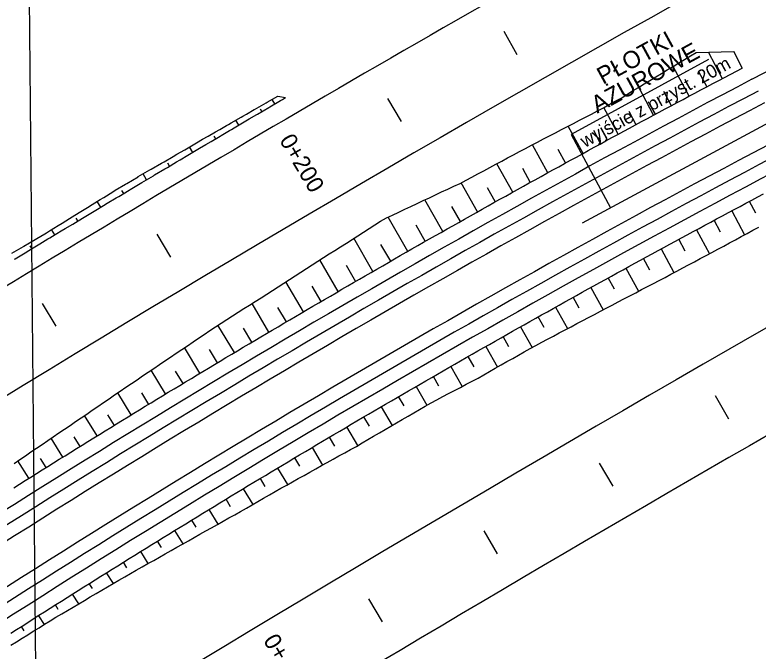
# Model space of a CAD drawing. Extents: x 6503541 to 6503743, y 5888004 to 5888145.
# Drawn here: x 6503601.663 to 6503602.995, y 5888053.81 to 5888054.951 of the extents above; entities that cross this region are included whole.
import ezdxf

# ---------------------------------------------------------------- set-up
doc = ezdxf.new("R2010")
doc.units = 0
doc.layers.add('12', color=7, linetype='Continuous')
doc.layers.add('tabela', color=7, linetype='Continuous')

msp = doc.modelspace()

# ---------------------------------------------------------------- linework, layer by layer
at = {"layer": '12'}
for p, q in [((6503602.9314, 5888054.836), (6503602.9062, 5888054.8841)), ((6503602.9669, 5888054.8556), (6503602.9514, 5888054.8851)), ((6503602.9514, 5888054.8851), (6503602.9669, 5888054.8556)), ((6503602.9065, 5888054.8707), (6503602.66, 5888054.7363)), ((6503602.9841, 5888054.8354), (6503603.0601, 5888054.8753)), ((6503602.8714, 5888054.8051), (6503602.8429, 5888054.8586)), ((6503602.8885, 5888054.8496), (6503602.9032, 5888054.822)), ((6503602.8079, 5888054.7711), (6503602.7811, 5888054.821)), ((6503602.8258, 5888054.814), (6503602.8396, 5888054.7882)), ((6503602.7446, 5888054.7369), (6503602.7187, 5888054.7847)), ((6503602.7632, 5888054.7781), (6503602.7762, 5888054.7541)), ((6503603.0226, 5888054.7621), (6503602.6797, 5888054.5776)), ((6503602.6813, 5888054.7025), (6503602.6546, 5888054.7514)), ((6503602.66, 5888054.7363), (6503602.7307, 5888054.605)), ((6503602.6998, 5888054.7439), (6503602.7129, 5888054.7197)), ((6503602.6182, 5888054.6678), (6503602.5906, 5888054.7178)), ((6503602.6362, 5888054.7099), (6503602.6498, 5888054.6852)), ((6503602.5552, 5888054.6329), (6503602.5268, 5888054.684)), ((6503602.5727, 5888054.6757), (6503602.5867, 5888054.6504)), ((6503602.4924, 5888054.5978), (6503602.4631, 5888054.6499)), ((6503602.5094, 5888054.6411), (6503602.5238, 5888054.6154)), ((6503602.4297, 5888054.5624), (6503602.3975, 5888054.6191)), ((6503602.9913, 5888054.595), (6503602.9798, 5888054.6165)), ((6503602.4457, 5888054.6073), (6503602.461, 5888054.5801)), ((6503602.3671, 5888054.5268), (6503602.332, 5888054.5882)), ((6503602.948, 5888054.5996), (6503602.971, 5888054.5565)), ((6503602.9279, 5888054.561), (6503602.9163, 5888054.5826)), ((6503602.3816, 5888054.5741), (6503602.3984, 5888054.5446)), ((6503602.8846, 5888054.5655), (6503602.9078, 5888054.5225)), ((6503602.3047, 5888054.4909), (6503602.2705, 5888054.5502)), ((6503602.8645, 5888054.527), (6503602.8529, 5888054.5484)), ((6503602.3185, 5888054.5393), (6503602.3359, 5888054.5089)), ((6503602.8213, 5888054.5312), (6503602.8444, 5888054.4887)), ((6503602.2424, 5888054.4549), (6503602.2095, 5888054.5113)), ((6503602.8012, 5888054.4929), (6503602.7897, 5888054.514)), ((6503602.2567, 5888054.5019), (6503602.2735, 5888054.4729)), ((6503602.7581, 5888054.4966), (6503602.7809, 5888054.4553)), ((6503602.1802, 5888054.4186), (6503602.1487, 5888054.4722)), ((6503602.7378, 5888054.4589), (6503602.7266, 5888054.4793)), ((6503602.1952, 5888054.4643), (6503602.2113, 5888054.4367)), ((6503602.6951, 5888054.4619), (6503602.7172, 5888054.4219)), ((6503602.6745, 5888054.4248), (6503602.6636, 5888054.4444)), ((6503602.1182, 5888054.382), (6503602.0879, 5888054.4332)), ((6503602.1338, 5888054.4264), (6503602.1492, 5888054.4003)), ((6503602.6322, 5888054.4269), (6503602.6537, 5888054.3884)), ((6503602.6114, 5888054.3904), (6503602.6008, 5888054.4093)), ((6503602.0563, 5888054.3452), (6503602.0269, 5888054.3944)), ((6503602.0722, 5888054.3888), (6503602.0872, 5888054.3637)), ((6503602.5694, 5888054.3916), (6503602.5903, 5888054.3546)), ((6503602.5485, 5888054.3555), (6503602.5381, 5888054.3739)), ((6503601.9945, 5888054.3082), (6503601.9669, 5888054.3541)), ((6503602.0111, 5888054.3505), (6503602.0254, 5888054.3268)), ((6503602.5068, 5888054.3561), (6503602.5277, 5888054.3193)), ((6503602.486, 5888054.3199), (6503602.4755, 5888054.3383)), ((6503601.9329, 5888054.271), (6503601.907, 5888054.3137)), ((6503601.9503, 5888054.3118), (6503601.9637, 5888054.2897)), ((6503602.4442, 5888054.3204), (6503602.4648, 5888054.2846)), ((6503602.423, 5888054.2851), (6503602.413, 5888054.3024)), ((6503602.3819, 5888054.2844), (6503602.4014, 5888054.2508)), ((6503601.8714, 5888054.2335), (6503601.8472, 5888054.2731)), ((6503601.8896, 5888054.2729), (6503601.9021, 5888054.2523)), ((6503602.3605, 5888054.2496), (6503602.3507, 5888054.2663)), ((6503602.3196, 5888054.2482), (6503602.3392, 5888054.2147)), ((6503601.81, 5888054.1959), (6503601.7875, 5888054.2323)), ((6503601.829, 5888054.2337), (6503601.8407, 5888054.2147)), ((6503602.2984, 5888054.2133), (6503602.2886, 5888054.23)), ((6503602.2575, 5888054.2118), (6503602.2772, 5888054.1784)), ((6503601.7488, 5888054.1579), (6503601.7278, 5888054.1917)), ((6503601.7686, 5888054.1944), (6503601.7794, 5888054.1769)), ((6503602.2362, 5888054.1772), (6503602.2265, 5888054.1935)), ((6503602.1956, 5888054.1751), (6503602.2144, 5888054.1435)), ((6503601.6878, 5888054.1198), (6503601.6682, 5888054.151)), ((6503601.7081, 5888054.1551), (6503601.7183, 5888054.1389)), ((6503602.1738, 5888054.1414), (6503602.1646, 5888054.1567)), ((6503602.1337, 5888054.1382), (6503602.1516, 5888054.1084)), ((6503602.1116, 5888054.1052), (6503602.1029, 5888054.1197)), ((6503602.072, 5888054.1011), (6503602.0892, 5888054.0728)), ((6503602.0496, 5888054.0687), (6503602.0413, 5888054.0825)), ((6503602.0105, 5888054.0637), (6503602.0265, 5888054.0374)), ((6503601.9875, 5888054.0324), (6503601.9798, 5888054.045)), ((6503601.9491, 5888054.0261), (6503601.9639, 5888054.0021)), ((6503601.9255, 5888053.9958), (6503601.9184, 5888054.0073)), ((6503601.8878, 5888053.9883), (6503601.9012, 5888053.9667)), ((6503601.8636, 5888053.9592), (6503601.8573, 5888053.9693)), ((6503601.8267, 5888053.9503), (6503601.8387, 5888053.9311)), ((6503601.802, 5888053.922), (6503601.7962, 5888053.9311)), ((6503601.7657, 5888053.912), (6503601.7768, 5888053.8945)), ((6503601.7406, 5888053.8844), (6503601.7353, 5888053.8927)), ((6503601.7049, 5888053.8734), (6503601.7151, 5888053.8574)), ((6503601.6795, 5888053.8463), (6503601.6745, 5888053.8541))]:
    msp.add_line(p, q, dxfattribs=at)
for points in [[(6503602.5635, 5888054.8792), (6503602.5397, 5888054.9209)], [(6503601.6616, 5888054.1465), (6503601.6716, 5888054.1534), (6503601.6816, 5888054.1602), (6503601.6916, 5888054.167), (6503601.7016, 5888054.1738), (6503601.7116, 5888054.1807), (6503601.7216, 5888054.1875), (6503601.7316, 5888054.1943), (6503601.7416, 5888054.2011), (6503601.7516, 5888054.2078), (6503601.7617, 5888054.2146), (6503601.7717, 5888054.2214), (6503601.7817, 5888054.2283), (6503601.7916, 5888054.2351), (6503601.8016, 5888054.242), (6503601.8116, 5888054.2488), (6503601.8216, 5888054.2557), (6503601.8316, 5888054.2625), (6503601.8416, 5888054.2693), (6503601.8516, 5888054.2762), (6503601.8616, 5888054.283), (6503601.8716, 5888054.2898), (6503601.8817, 5888054.2966), (6503601.8917, 5888054.3034), (6503601.9017, 5888054.3102), (6503601.9118, 5888054.317), (6503601.9218, 5888054.3237), (6503601.9318, 5888054.3305), (6503601.9419, 5888054.3373), (6503601.9519, 5888054.3441), (6503601.962, 5888054.3508), (6503601.972, 5888054.3576), (6503601.9821, 5888054.3644), (6503601.9921, 5888054.3711), (6503602.0022, 5888054.3779), (6503602.0123, 5888054.3846), (6503602.0223, 5888054.3914), (6503602.0324, 5888054.3981), (6503602.0426, 5888054.4047), (6503602.0528, 5888054.4111), (6503602.0631, 5888054.4176), (6503602.0733, 5888054.4241), (6503602.0836, 5888054.4305), (6503602.0938, 5888054.4369), (6503602.1041, 5888054.4434), (6503602.1143, 5888054.4499), (6503602.1245, 5888054.4565), (6503602.1346, 5888054.463), (6503602.1448, 5888054.4696), (6503602.155, 5888054.4762), (6503602.1652, 5888054.4828), (6503602.1754, 5888054.4894), (6503602.1855, 5888054.4959), (6503602.1957, 5888054.5025), (6503602.2059, 5888054.509), (6503602.2161, 5888054.5156), (6503602.2264, 5888054.5221), (6503602.2366, 5888054.5286), (6503602.2468, 5888054.5351), (6503602.257, 5888054.5417), (6503602.2672, 5888054.5482), (6503602.2775, 5888054.5547), (6503602.2877, 5888054.5612), (6503602.2979, 5888054.5677), (6503602.3082, 5888054.5742), (6503602.3184, 5888054.5807), (6503602.3289, 5888054.5867), (6503602.3399, 5888054.5919), (6503602.3509, 5888054.5971), (6503602.3618, 5888054.6023), (6503602.3728, 5888054.6075), (6503602.3838, 5888054.6127), (6503602.3948, 5888054.6178), (6503602.4058, 5888054.623), (6503602.4168, 5888054.6282), (6503602.4278, 5888054.6333), (6503602.4388, 5888054.6385), (6503602.4498, 5888054.6436), (6503602.4608, 5888054.6487), (6503602.4716, 5888054.6542), (6503602.4822, 5888054.66), (6503602.4929, 5888054.6657), (6503602.5035, 5888054.6715), (6503602.5142, 5888054.6772), (6503602.5249, 5888054.6829), (6503602.5355, 5888054.6887), (6503602.5462, 5888054.6944), (6503602.5569, 5888054.7), (6503602.5676, 5888054.7057), (6503602.5783, 5888054.7113), (6503602.589, 5888054.717), (6503602.5997, 5888054.7226), (6503602.6104, 5888054.7283), (6503602.6212, 5888054.7339), (6503602.6319, 5888054.7395), (6503602.6426, 5888054.7451), (6503602.6533, 5888054.7507), (6503602.6641, 5888054.7563), (6503602.6748, 5888054.7619), (6503602.6855, 5888054.7675), (6503602.6963, 5888054.7731), (6503602.707, 5888054.7787), (6503602.7178, 5888054.7842), (6503602.7284, 5888054.79), (6503602.739, 5888054.7959), (6503602.7495, 5888054.8018), (6503602.7599, 5888054.808), (6503602.7703, 5888054.8144), (6503602.7806, 5888054.8207), (6503602.791, 5888054.827), (6503602.8013, 5888054.8333), (6503602.8117, 5888054.8396), (6503602.822, 5888054.8459), (6503602.8324, 5888054.8522), (6503602.8428, 5888054.8585), (6503602.8531, 5888054.8648), (6503602.8635, 5888054.871), (6503602.8739, 5888054.8773), (6503602.8843, 5888054.8836), (6503602.9514, 5888054.8851)], [(6503601.6606, 5888054.1027), (6503601.6708, 5888054.1092), (6503601.681, 5888054.1156), (6503601.6913, 5888054.122), (6503601.7015, 5888054.1284), (6503601.7117, 5888054.1348), (6503601.722, 5888054.1412), (6503601.7322, 5888054.1476), (6503601.7424, 5888054.154), (6503601.7527, 5888054.1603), (6503601.7629, 5888054.1667), (6503601.7732, 5888054.1731), (6503601.7835, 5888054.1794), (6503601.7937, 5888054.1858), (6503601.804, 5888054.1921), (6503601.8142, 5888054.1985), (6503601.8245, 5888054.2048), (6503601.8348, 5888054.2111), (6503601.8451, 5888054.2174), (6503601.8554, 5888054.2238), (6503601.8657, 5888054.2301), (6503601.876, 5888054.2364), (6503601.8863, 5888054.2426), (6503601.8966, 5888054.2489), (6503601.9069, 5888054.2552), (6503601.9172, 5888054.2615), (6503601.9275, 5888054.2678), (6503601.9378, 5888054.274), (6503601.9481, 5888054.2803), (6503601.9584, 5888054.2865), (6503601.9688, 5888054.2928), (6503601.9791, 5888054.299), (6503601.9894, 5888054.3052), (6503601.9998, 5888054.3114), (6503602.0101, 5888054.3176), (6503602.0205, 5888054.3239), (6503602.0308, 5888054.3301), (6503602.0412, 5888054.3363), (6503602.0515, 5888054.3424), (6503602.0619, 5888054.3486), (6503602.0723, 5888054.3548), (6503602.0827, 5888054.361), (6503602.093, 5888054.3671), (6503602.1034, 5888054.3733), (6503602.1138, 5888054.3794), (6503602.1242, 5888054.3856), (6503602.1346, 5888054.3917), (6503602.145, 5888054.3979), (6503602.1554, 5888054.404), (6503602.1658, 5888054.4101), (6503602.1762, 5888054.4162), (6503602.1866, 5888054.4223), (6503602.197, 5888054.4284), (6503602.2074, 5888054.4345), (6503602.2178, 5888054.4406), (6503602.2283, 5888054.4467), (6503602.2387, 5888054.4527), (6503602.2491, 5888054.4588), (6503602.2596, 5888054.4649), (6503602.27, 5888054.4709), (6503602.2804, 5888054.477), (6503602.2909, 5888054.483), (6503602.3013, 5888054.489), (6503602.3118, 5888054.4951), (6503602.3223, 5888054.5011), (6503602.3327, 5888054.5071), (6503602.3432, 5888054.5131), (6503602.3537, 5888054.5191), (6503602.3641, 5888054.5251), (6503602.3746, 5888054.5311), (6503602.3851, 5888054.5371), (6503602.3956, 5888054.543), (6503602.4061, 5888054.549), (6503602.4166, 5888054.555), (6503602.4271, 5888054.5609), (6503602.4376, 5888054.5669), (6503602.4481, 5888054.5728), (6503602.4586, 5888054.5787), (6503602.4691, 5888054.5847), (6503602.4796, 5888054.5906), (6503602.4901, 5888054.5965), (6503602.5006, 5888054.6024), (6503602.5112, 5888054.6083), (6503602.5217, 5888054.6142), (6503602.5322, 5888054.6201), (6503602.5428, 5888054.626), (6503602.5533, 5888054.6318), (6503602.5639, 5888054.6377), (6503602.5744, 5888054.6436), (6503602.585, 5888054.6494), (6503602.5955, 5888054.6553), (6503602.6061, 5888054.6611), (6503602.6166, 5888054.667), (6503602.6272, 5888054.6728), (6503602.6378, 5888054.6786), (6503602.6483, 5888054.6844), (6503602.6589, 5888054.6902), (6503602.6695, 5888054.696), (6503602.6801, 5888054.7018), (6503602.6907, 5888054.7076), (6503602.7013, 5888054.7134), (6503602.7119, 5888054.7192), (6503602.7225, 5888054.725), (6503602.7331, 5888054.7307), (6503602.7437, 5888054.7365), (6503602.7543, 5888054.7422), (6503602.7649, 5888054.748), (6503602.7755, 5888054.7537), (6503602.7861, 5888054.7594), (6503602.7968, 5888054.7652), (6503602.8074, 5888054.7709), (6503602.818, 5888054.7766), (6503602.8287, 5888054.7823), (6503602.8393, 5888054.788), (6503602.8499, 5888054.7937), (6503602.8606, 5888054.7994), (6503602.8712, 5888054.805), (6503602.8819, 5888054.8107), (6503602.8925, 5888054.8164), (6503602.9032, 5888054.822), (6503602.9139, 5888054.8277), (6503602.9245, 5888054.8333), (6503602.9669, 5888054.8556)], [(6503601.6574, 5888054.5234), (6503601.6782, 5888054.5357), (6503601.6789, 5888054.5361), (6503601.6989, 5888054.5479), (6503601.7019, 5888054.5497), (6503601.7166, 5888054.5584), (6503601.7196, 5888054.5603), (6503601.7247, 5888054.5634), (6503601.7401, 5888054.573), (6503601.7474, 5888054.5775), (6503601.7605, 5888054.5856), (6503601.7701, 5888054.5915), (6503601.781, 5888054.5983), (6503601.7927, 5888054.6055), (6503601.8015, 5888054.6109), (6503601.8154, 5888054.6196), (6503601.822, 5888054.6236), (6503601.8381, 5888054.6337), (6503601.8424, 5888054.6364), (6503601.861, 5888054.6473), (6503601.8632, 5888054.6486), (6503601.884, 5888054.6607), (6503601.884, 5888054.6608), (6503601.9048, 5888054.6729), (6503601.9071, 5888054.6742), (6503601.9256, 5888054.685), (6503601.9301, 5888054.6876), (6503601.9465, 5888054.6971), (6503601.9532, 5888054.701), (6503601.9673, 5888054.7091), (6503601.9763, 5888054.7143), (6503601.9882, 5888054.7212), (6503601.9994, 5888054.7277), (6503602.009, 5888054.7333), (6503602.0225, 5888054.741), (6503602.0299, 5888054.7453), (6503602.0423, 5888054.7525), (6503602.0456, 5888054.7543), (6503602.0507, 5888054.7573), (6503602.0687, 5888054.7677), (6503602.0716, 5888054.7693), (6503602.0778, 5888054.7729), (6503602.0918, 5888054.781), (6503602.0925, 5888054.7814), (6503602.1133, 5888054.7933), (6503602.1134, 5888054.7934), (6503602.1149, 5888054.7942), (6503602.1342, 5888054.8054), (6503602.1481, 5888054.8025)], [(6503601.6619, 5888054.5127), (6503601.6634, 5888054.5136), (6503601.684, 5888054.526), (6503601.6847, 5888054.5265), (6503601.7046, 5888054.5385), (6503601.7075, 5888054.5403), (6503601.7221, 5888054.5491), (6503601.7252, 5888054.551), (6503601.7304, 5888054.5541), (6503601.7458, 5888054.5634), (6503601.7532, 5888054.5678), (6503601.7664, 5888054.5758), (6503601.776, 5888054.5816), (6503601.7871, 5888054.5882), (6503601.7989, 5888054.5953), (6503601.8077, 5888054.6006), (6503601.8217, 5888054.6091), (6503601.8284, 5888054.613), (6503601.8446, 5888054.6228), (6503601.849, 5888054.6254), (6503601.8675, 5888054.6365), (6503601.8697, 5888054.6378), (6503601.8903, 5888054.6501), (6503601.8904, 5888054.6501), (6503601.911, 5888054.6624), (6503601.9133, 5888054.6638), (6503601.9317, 5888054.6748), (6503601.9362, 5888054.6774), (6503601.9524, 5888054.6871), (6503601.9591, 5888054.691), (6503601.9731, 5888054.6994), (6503601.982, 5888054.7047), (6503601.9938, 5888054.7116), (6503602.005, 5888054.7182), (6503602.0145, 5888054.7239), (6503602.0279, 5888054.7318), (6503602.0353, 5888054.7362), (6503602.0476, 5888054.7434), (6503602.0509, 5888054.7454), (6503602.056, 5888054.7484), (6503602.0738, 5888054.7589), (6503602.0767, 5888054.7606), (6503602.0829, 5888054.7642), (6503602.0968, 5888054.7724), (6503602.0975, 5888054.7728), (6503602.1182, 5888054.785), (6503602.1183, 5888054.785), (6503602.1198, 5888054.7859), (6503602.139, 5888054.7972), (6503602.1428, 5888054.7994), (6503602.1481, 5888054.8025)], [(6503602.3557, 5888054.7596), (6503602.3316, 5888054.8011)], [(6503602.1286, 5888054.7911), (6503602.1238, 5888054.7993)], [(6503602.1055, 5888054.7775), (6503602.103, 5888054.7818)], [(6503602.0642, 5888054.7532), (6503602.0589, 5888054.762)], [(6503602.0228, 5888054.7288), (6503602.0201, 5888054.7334)], [(6503601.9815, 5888054.7043), (6503601.9758, 5888054.714)], [(6503601.9402, 5888054.6798), (6503601.9372, 5888054.6849)], [(6503601.899, 5888054.6553), (6503601.8927, 5888054.6658)], [(6503601.6556, 5888053.842), (6503601.6656, 5888053.8484), (6503601.6757, 5888053.8548), (6503601.6858, 5888053.8613), (6503601.6958, 5888053.8677), (6503601.7059, 5888053.8741), (6503601.716, 5888053.8805), (6503601.726, 5888053.8869), (6503601.7361, 5888053.8933), (6503601.7462, 5888053.8996), (6503601.7563, 5888053.906), (6503601.7664, 5888053.9124), (6503601.7765, 5888053.9187), (6503601.7866, 5888053.9251), (6503601.7967, 5888053.9314), (6503601.8068, 5888053.9378), (6503601.8169, 5888053.9441), (6503601.827, 5888053.9504), (6503601.8371, 5888053.9568), (6503601.8472, 5888053.9631), (6503601.8574, 5888053.9694), (6503601.8675, 5888053.9757), (6503601.8776, 5888053.982), (6503601.8878, 5888053.9883), (6503601.8979, 5888053.9946), (6503601.9081, 5888054.0009), (6503601.9182, 5888054.0071), (6503601.9284, 5888054.0134), (6503601.9385, 5888054.0196), (6503601.9487, 5888054.0259), (6503601.9589, 5888054.0321), (6503601.969, 5888054.0384), (6503601.9792, 5888054.0446), (6503601.9894, 5888054.0509), (6503601.9996, 5888054.0571), (6503602.0097, 5888054.0633), (6503602.0199, 5888054.0695), (6503602.0301, 5888054.0757), (6503602.0403, 5888054.0819), (6503602.0505, 5888054.0881), (6503602.0607, 5888054.0943), (6503602.0709, 5888054.1004), (6503602.0812, 5888054.1066), (6503602.0914, 5888054.1128), (6503602.1016, 5888054.1189), (6503602.1118, 5888054.1251), (6503602.122, 5888054.1312), (6503602.1323, 5888054.1374), (6503602.1425, 5888054.1435), (6503602.1528, 5888054.1496), (6503602.163, 5888054.1557), (6503602.1732, 5888054.1619), (6503602.1835, 5888054.168), (6503602.1937, 5888054.1741), (6503602.204, 5888054.1802), (6503602.2143, 5888054.1862), (6503602.2245, 5888054.1923), (6503602.2348, 5888054.1984), (6503602.2451, 5888054.2045), (6503602.2554, 5888054.2105), (6503602.2656, 5888054.2166), (6503602.2759, 5888054.2226), (6503602.2862, 5888054.2287), (6503602.2965, 5888054.2347), (6503602.3068, 5888054.2407), (6503602.3171, 5888054.2468), (6503602.3274, 5888054.2528), (6503602.3377, 5888054.2588), (6503602.348, 5888054.2648), (6503602.3583, 5888054.2708), (6503602.3687, 5888054.2768), (6503602.379, 5888054.2828), (6503602.3893, 5888054.2887), (6503602.3996, 5888054.2947), (6503602.41, 5888054.3007), (6503602.4203, 5888054.3066), (6503602.4307, 5888054.3126), (6503602.441, 5888054.3185), (6503602.4514, 5888054.3245), (6503602.4617, 5888054.3304), (6503602.4721, 5888054.3363), (6503602.4824, 5888054.3423), (6503602.4928, 5888054.3482), (6503602.5032, 5888054.3541), (6503602.5135, 5888054.36), (6503602.5239, 5888054.3659), (6503602.5343, 5888054.3718), (6503602.5447, 5888054.3776), (6503602.555, 5888054.3835), (6503602.5654, 5888054.3894), (6503602.5758, 5888054.3952), (6503602.5862, 5888054.4011), (6503602.5966, 5888054.4069), (6503602.607, 5888054.4128), (6503602.6174, 5888054.4186), (6503602.6279, 5888054.4244), (6503602.6383, 5888054.4303), (6503602.6487, 5888054.4361), (6503602.6591, 5888054.4419), (6503602.6695, 5888054.4477), (6503602.68, 5888054.4535), (6503602.6904, 5888054.4593), (6503602.7008, 5888054.4651), (6503602.7113, 5888054.4708), (6503602.7217, 5888054.4766), (6503602.7322, 5888054.4824), (6503602.7426, 5888054.4881), (6503602.7531, 5888054.4939), (6503602.7635, 5888054.4996), (6503602.774, 5888054.5054), (6503602.7845, 5888054.5111), (6503602.7949, 5888054.5168), (6503602.8054, 5888054.5225), (6503602.8159, 5888054.5282), (6503602.8264, 5888054.534), (6503602.8368, 5888054.5396), (6503602.8473, 5888054.5453), (6503602.8578, 5888054.551), (6503602.8683, 5888054.5567), (6503602.8788, 5888054.5624), (6503602.8893, 5888054.568), (6503602.8998, 5888054.5737), (6503602.9103, 5888054.5794), (6503602.9208, 5888054.585), (6503602.9314, 5888054.5906), (6503602.9419, 5888054.5963), (6503602.9524, 5888054.6019), (6503602.9629, 5888054.6075), (6503602.9734, 5888054.6131), (6503602.984, 5888054.6187), (6503602.9945, 5888054.6243), (6503603.0051, 5888054.6299)], [(6503601.8578, 5888054.6307), (6503601.8545, 5888054.6361)], [(6503601.8166, 5888054.606), (6503601.8104, 5888054.6164)], [(6503601.7755, 5888054.5813), (6503601.7725, 5888054.5862)], [(6503601.6553, 5888053.8203), (6503601.6654, 5888053.8266), (6503601.6756, 5888053.8329), (6503601.6857, 5888053.8392), (6503601.6958, 5888053.8455), (6503601.706, 5888053.8517), (6503601.7161, 5888053.858), (6503601.7263, 5888053.8642), (6503601.7364, 5888053.8705), (6503601.7467, 5888053.8766), (6503601.7569, 5888053.8827), (6503601.7672, 5888053.8888), (6503601.7774, 5888053.8948), (6503601.7877, 5888053.9009), (6503601.7979, 5888053.907), (6503601.8082, 5888053.9131), (6503601.8185, 5888053.9191), (6503601.8287, 5888053.9252), (6503601.839, 5888053.9312), (6503601.8493, 5888053.9373), (6503601.8596, 5888053.9433), (6503601.87, 5888053.9492), (6503601.8804, 5888053.955), (6503601.8908, 5888053.9608), (6503601.9012, 5888053.9667), (6503601.9116, 5888053.9725), (6503601.922, 5888053.9784), (6503601.9323, 5888053.9843), (6503601.9427, 5888053.9901), (6503601.9531, 5888053.996), (6503601.9635, 5888054.0019), (6503601.9738, 5888054.0078), (6503601.9842, 5888054.0136), (6503601.9946, 5888054.0195), (6503602.005, 5888054.0253), (6503602.0154, 5888054.0312), (6503602.0258, 5888054.037), (6503602.0362, 5888054.0428), (6503602.0466, 5888054.0486), (6503602.057, 5888054.0545), (6503602.0674, 5888054.0603), (6503602.0777, 5888054.0662), (6503602.088, 5888054.0722), (6503602.0984, 5888054.0781), (6503602.1087, 5888054.084), (6503602.119, 5888054.09), (6503602.1294, 5888054.0959), (6503602.1397, 5888054.1018), (6503602.1501, 5888054.1076), (6503602.1605, 5888054.1134), (6503602.1709, 5888054.1193), (6503602.1813, 5888054.1251), (6503602.1917, 5888054.1309), (6503602.2021, 5888054.1367), (6503602.2125, 5888054.1425), (6503602.2229, 5888054.1483), (6503602.2334, 5888054.154), (6503602.2438, 5888054.1598), (6503602.2542, 5888054.1656), (6503602.2646, 5888054.1713), (6503602.2751, 5888054.1771), (6503602.2854, 5888054.1831), (6503602.2956, 5888054.1891), (6503602.3059, 5888054.1951), (6503602.3162, 5888054.2012), (6503602.3264, 5888054.2072), (6503602.3367, 5888054.2132), (6503602.347, 5888054.2192), (6503602.3573, 5888054.2252), (6503602.3676, 5888054.2312), (6503602.3779, 5888054.2372), (6503602.3882, 5888054.2432), (6503602.3985, 5888054.2491), (6503602.4088, 5888054.255), (6503602.4193, 5888054.2606), (6503602.4299, 5888054.2662), (6503602.4404, 5888054.2717), (6503602.451, 5888054.2773), (6503602.4615, 5888054.2828), (6503602.472, 5888054.2884), (6503602.4826, 5888054.2939), (6503602.4931, 5888054.2995), (6503602.5035, 5888054.3054), (6503602.5138, 5888054.3113), (6503602.5241, 5888054.3172), (6503602.5345, 5888054.3231), (6503602.5448, 5888054.329), (6503602.5552, 5888054.3349), (6503602.5655, 5888054.3408), (6503602.5759, 5888054.3466), (6503602.5863, 5888054.3525), (6503602.5968, 5888054.3581), (6503602.6073, 5888054.3637), (6503602.6178, 5888054.3693), (6503602.6283, 5888054.3749), (6503602.6388, 5888054.3805), (6503602.6493, 5888054.386), (6503602.6599, 5888054.3916), (6503602.6704, 5888054.3972), (6503602.6809, 5888054.4027), (6503602.6914, 5888054.4083), (6503602.702, 5888054.4138), (6503602.7125, 5888054.4194), (6503602.723, 5888054.4249), (6503602.7336, 5888054.4305), (6503602.7441, 5888054.436), (6503602.7547, 5888054.4416), (6503602.7652, 5888054.4471), (6503602.7758, 5888054.4526), (6503602.7863, 5888054.4581), (6503602.7969, 5888054.4636), (6503602.8074, 5888054.4691), (6503602.818, 5888054.4746), (6503602.8285, 5888054.4802), (6503602.839, 5888054.4858), (6503602.8495, 5888054.4914), (6503602.86, 5888054.497), (6503602.8705, 5888054.5026), (6503602.881, 5888054.5082), (6503602.8915, 5888054.5138), (6503602.902, 5888054.5194), (6503602.9125, 5888054.525), (6503602.923, 5888054.5306), (6503602.9335, 5888054.5363), (6503602.9439, 5888054.5419), (6503602.9544, 5888054.5476), (6503602.9649, 5888054.5532), (6503602.9754, 5888054.5588), (6503602.9859, 5888054.5645), (6503602.9964, 5888054.5701)], [(6503601.7344, 5888054.5565), (6503601.7287, 5888054.5659)], [(6503601.9423, 5888054.5162), (6503601.9177, 5888054.5574)], [(6503601.6933, 5888054.5317), (6503601.6904, 5888054.5364)], [(6503601.7369, 5888054.3925), (6503601.712, 5888054.4335)], [(6503602.9426, 5888054.2261), (6503602.9186, 5888054.2677)], [(6503602.7351, 5888054.1057), (6503602.711, 5888054.1472)], [(6503602.5282, 5888053.9844), (6503602.5038, 5888054.0257)], [(6503602.3218, 5888053.8621), (6503602.2972, 5888053.9034)]]:
    msp.add_lwpolyline(points, dxfattribs=at)
for centre, radius, start, end in [((6503620.5817, 5888023.3322), 36.27, 116.09163, 121.5843), ((6503629.9308, 5888007.4817), 53.916, 117.58603, 123.39571), ((6503620.5817, 5888023.3322), 36.438, 118.93897, 121.6677), ((6503611.9485, 5888037.7631), 19.2828, 117.70332, 123.39571), ((6503611.9485, 5888037.7631), 19.2588, 117.70332, 123.39571), ((6503611.9485, 5888037.7631), 19.2348, 117.70332, 123.39571), ((6503611.9485, 5888037.7631), 19.1652, 117.70332, 123.39571), ((6503611.9485, 5888037.7631), 19.1172, 117.44544, 123.39571), ((6503611.9485, 5888037.7631), 19.1412, 117.70332, 123.39571), ((6503629.9308, 5888007.4817), 54.084, 119.63838, 123.39571)]:
    msp.add_arc(centre, radius, start, end, dxfattribs=at)
at = {"layer": 'tabela'}
msp.add_line((6503601.7206, 5888051.5997), (6503601.6737, 5888056.6198), dxfattribs=at)
msp.add_line((6503601.7206, 5888051.5997), (6503601.6737, 5888056.6198), dxfattribs=at)

# ---------------------------------------------------------------- texts
at = {"layer": '12'}
for s, height, rotation, p in [('PŁOTKI', 0.0311, 28.6942, (6503602.7172, 5888054.8251)), ('AŻUROWE', 0.0311, 28.6942, (6503602.7068, 5888054.7736)), ('wyjście z przyst. 20m', 0.023802, 28.6942, (6503602.6847, 5888054.7122)), ('0+200', 0.03, 300.4882, (6503602.1361, 5888054.7262)), ('0+400', 0.03, 301.0189, (6503602.1071, 5888053.8291))]:
    msp.add_text(s, height=height, rotation=rotation, dxfattribs=at).set_placement(p)

doc.saveas('drawing.dxf')
